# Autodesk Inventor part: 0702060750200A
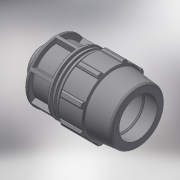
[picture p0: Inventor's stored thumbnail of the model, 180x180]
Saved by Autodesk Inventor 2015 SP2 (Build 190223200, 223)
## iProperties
Created: 2017-02
Part Number: 0702060750200A
Material: Generic
Description: PLASSON MALE ADAPTOR 75-2"
Document SubType Name: Modeling
Designer: KIM
Mass: 964.158 g
Surface Area: 1468.9 cm^2
Volume: 964.158 cm^3
Density: 1 g/cm^3
Appearance: Default
Author: KIM
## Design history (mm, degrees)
derived "87020.ipt"
feature "Solid1::87020.ipt"
tag "TaggingFeature1"
body "Solid1"
other parameters: "d2" = 75, "d4" = 26.85714, "d5" = 47, "d7" = 132, "d8" = 99, "d9" = 26.85714, "d11" = 5.37143, "d12" = 105.6, "d13" = 120 deg, "d14" = 97.5, "d15" = 6 deg, "d16" = 118.8, "d18" = 3.75, "d19" = 35 deg, "d20" = 17.5 deg, "d21" = 122.76, "d23" = 0, "d25" = 360 deg, "d27" = 2.64, "d34" = 6.6, "d36" = 0, "d42" = 47, "d43" = 3.96, "d46" = 2.25, "d51" = 188, "d52" = 26, "d53" = 1.5, "d55" = 360 deg, "d57" = 59.614, "d58" = 41.7298, "d59" = 37.6, "d61" = 116.424, "d62" = 3.93143, "d63" = 3.93143, "d66" = 7.86286, "d_" = 75, "E_" = 132, "H_" = 188, "l_2" = 26, "R_" = 59.614, "d60" = 19.65714
